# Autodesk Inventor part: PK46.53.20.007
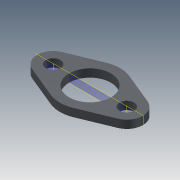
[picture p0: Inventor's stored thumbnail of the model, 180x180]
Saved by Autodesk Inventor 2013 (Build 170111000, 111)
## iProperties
Created: 2005-03
Part Number: PK46.53.20.007
Material: Steel, Mild
Document SubType Name: Modeling
Designer: HKostja
Manufacturer: Standard
Standards Organization: Custom
Density: 7.86 g/cm^3
Mass: 338.113 g
Surface Area: 145.993 cm^2
Volume: 43.0169 cm^3
Author: HKostja
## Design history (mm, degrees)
sketch "Эскиз1"
  geometry: L1 (-46, 0)-(46, 0); L2 (-53.609, 18.496)-(-14.266, 34.68); L3 (14.266, 34.68)-(53.609, 18.496); L4 (53.609, -18.496)-(14.266, -34.68); L5 (-14.266, -34.68)-(-53.609, -18.496); C1 r 26 at (0, 0); C2 r 9 at (-46, 0); C3 r 9 at (46, 0); A1 r 20 centre (-46, 0) between (-53.609, 18.496) and (-53.609, -18.496); A2 r 20 centre (46, 0) between (53.609, -18.496) and (53.609, 18.496); A3 r 37.5 centre (0, 0) between (-14.266, -34.68) and (14.266, -34.68); A4 r 37.5 centre (0, 0) between (14.266, 34.68) and (-14.266, 34.68); 1 further point
  constraints: 10 end point, 8 point on circle, 8 tangent, 7 centre point, 6 coincident, 3 equal radius, 1 horizontal, 1 midpoint, 1 other
  dimensions: "d0" = 52 diameter of C1; "d1" = 18 diameter of C2; "d2" = 92 distance of L1.end C2.centre; "d3" = 37.5 radius of A4; "d4" = 20 radius of A1
extrude "Выдавливание1" new body sketch "Эскиз1" distance "d5" = 10; taper "d6" = 0 deg
node "РабОсь1"
node "РабОсь2"
node "РабПлоскость1"
body "Solid1"
